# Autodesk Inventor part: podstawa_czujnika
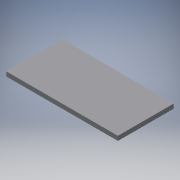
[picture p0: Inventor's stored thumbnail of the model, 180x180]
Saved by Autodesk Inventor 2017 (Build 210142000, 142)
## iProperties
Created: 2021-01
Part Number: podstawa_czujnika
Material: Generic
Document SubType Name: Modeling
Designer: WindowsX
Density: 1 g/cm^3
Appearance: Default
Author: WindowsX
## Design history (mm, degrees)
sketch "Szkic1"
  geometry: L1 (0, 0)-(76, 0); L2 (76, 0)-(76, 38); L3 (76, 38)-(0, 38); L4 (0, 38)-(0, 0)
  constraints: 8 end point, 2 parallel, 1 horizontal, 1 perpendicular
extrude "Wyciągnięcie proste1" new body sketch "Szkic1" distance "d0" = 3; taper "d1" = 0 deg
node "Bryła1"
